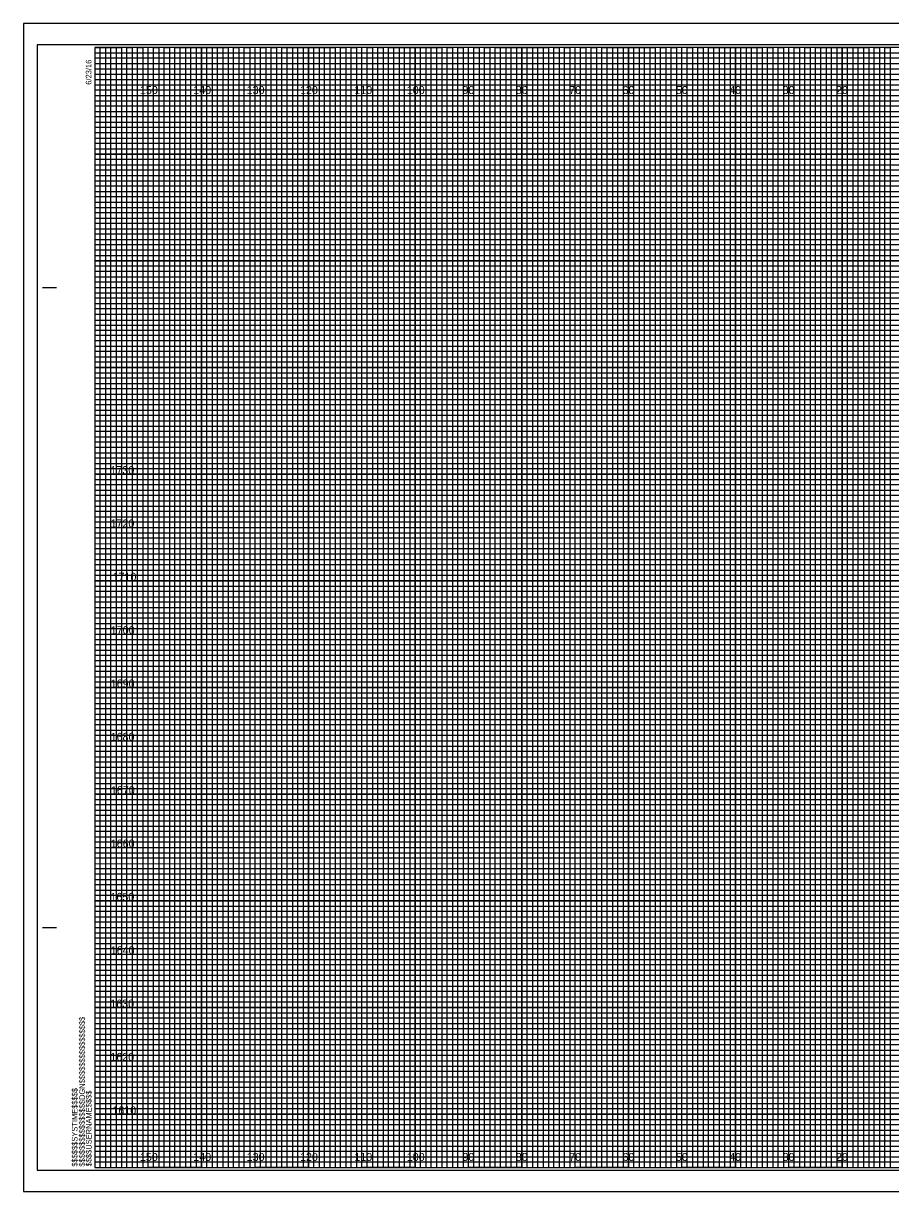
# Model space of a CAD drawing. Extents: x -13 to 323, y 435 to 654.
# Drawn here: x -13.4 to 149.1, y 435.5 to 654.5 of the extents above; entities that cross this region are included whole.
import ezdxf

# ---------------------------------------------------------------- set-up
doc = ezdxf.new("R2010")
doc.units = 0
for name, color, linetype in [('Exist Horizontal Alignment', 7, 'Continuous'), ('Exist XS Center Line Elevation Label', 7, 'Continuous'), ('Exist XS Ground Line', 7, 'Continuous'), ('Prop Study Area', 7, 'Continuous'), ('Prop XS Finish Grade', 7, 'Continuous'), ('Prop XS Finish Grade Pavement', 7, 'Continuous'), ('Prop XS Pvmt Edge Slope', 7, 'Continuous'), ('Prop XS Subgrade Earthwork', 7, 'Continuous'), ('Scratch_Level_0', 7, 'Continuous'), ('Scratch_Level_5', 7, 'Continuous'), ('Typical Guardrail CELL', 7, 'Continuous')]:
    doc.layers.add(name, color=color, linetype=linetype)

msp = doc.modelspace()

# ---------------------------------------------------------------- linework, layer by layer
at = {"layer": 'Exist Horizontal Alignment'}
for points in [[(0, 650), (5, 650), (5, 440), (15, 440), (15, 650), (25, 650), (25, 440), (35, 440), (35, 650), (45, 650), (45, 440), (55, 440), (55, 650), (65, 650), (65, 440), (75, 440), (75, 650), (85, 650), (85, 440), (95, 440), (95, 650), (105, 650), (105, 440), (115, 440), (115, 650), (125, 650), (125, 440), (135, 440), (135, 650), (145, 650), (145, 440), (155, 440)], [(0, 645), (275, 645)], [(0, 625), (320, 625), (320, 635), (0, 635)], [(0, 605), (320, 605), (320, 615), (0, 615)], [(0, 585), (320, 585), (320, 595), (0, 595)], [(0, 565), (320, 565), (320, 575), (0, 575)], [(0, 545), (320, 545), (320, 555), (0, 555)], [(0, 525), (320, 525), (320, 535), (0, 535)], [(0, 505), (320, 505), (320, 515), (0, 515)], [(0, 485), (320, 485), (320, 495), (0, 495)], [(0, 465), (320, 465), (320, 475), (0, 475)], [(0, 445), (320, 445), (320, 455), (0, 455)]]:
    msp.add_lwpolyline(points, dxfattribs=at)
at = {"layer": 'Exist XS Center Line Elevation Label'}
for points in [[(0, 440), (1, 440), (1, 650), (2, 650), (2, 440)], [(2, 440), (3, 440), (3, 650), (4, 650), (4, 440)], [(5, 440), (6, 440), (6, 650), (7, 650), (7, 440)], [(7, 440), (8, 440), (8, 650), (9, 650), (9, 440)], [(10, 440), (11, 440), (11, 650), (12, 650), (12, 440)], [(12, 440), (13, 440), (13, 650), (14, 650), (14, 440)], [(15, 440), (16, 440), (16, 650), (17, 650), (17, 440)], [(17, 440), (18, 440), (18, 650), (19, 650), (19, 440)], [(20, 440), (21, 440), (21, 650), (22, 650), (22, 440)], [(22, 440), (23, 440), (23, 650), (24, 650), (24, 440)], [(25, 440), (26, 440), (26, 650), (27, 650), (27, 440)], [(27, 440), (28, 440), (28, 650), (29, 650), (29, 440)], [(30, 440), (31, 440), (31, 650), (32, 650), (32, 440)], [(32, 440), (33, 440), (33, 650), (34, 650), (34, 440)], [(35, 440), (36, 440), (36, 650), (37, 650), (37, 440)], [(37, 440), (38, 440), (38, 650), (39, 650), (39, 440)], [(40, 440), (41, 440), (41, 650), (42, 650), (42, 440)], [(42, 440), (43, 440), (43, 650), (44, 650), (44, 440)], [(45, 440), (46, 440), (46, 650), (47, 650), (47, 440)], [(47, 440), (48, 440), (48, 650), (49, 650), (49, 440)], [(50, 440), (51, 440), (51, 650), (52, 650), (52, 440)], [(52, 440), (53, 440), (53, 650), (54, 650), (54, 440)], [(55, 440), (56, 440), (56, 650), (57, 650), (57, 440)], [(57, 440), (58, 440), (58, 650), (59, 650), (59, 440)], [(60, 440), (61, 440), (61, 650), (62, 650), (62, 440)], [(62, 440), (63, 440), (63, 650), (64, 650), (64, 440)], [(65, 440), (66, 440), (66, 650), (67, 650), (67, 440)], [(67, 440), (68, 440), (68, 650), (69, 650), (69, 440)], [(70, 440), (71, 440), (71, 650), (72, 650), (72, 440)], [(72, 440), (73, 440), (73, 650), (74, 650), (74, 440)], [(75, 440), (76, 440), (76, 650), (77, 650), (77, 440)], [(77, 440), (78, 440), (78, 650), (79, 650), (79, 440)], [(80, 440), (81, 440), (81, 650), (82, 650), (82, 440)], [(82, 440), (83, 440), (83, 650), (84, 650), (84, 440)], [(85, 440), (86, 440), (86, 650), (87, 650), (87, 440)], [(87, 440), (88, 440), (88, 650), (89, 650), (89, 440)], [(90, 440), (91, 440), (91, 650), (92, 650), (92, 440)], [(92, 440), (93, 440), (93, 650), (94, 650), (94, 440)], [(95, 440), (96, 440), (96, 650), (97, 650), (97, 440)], [(97, 440), (98, 440), (98, 650), (99, 650), (99, 440)], [(100, 440), (101, 440), (101, 650), (102, 650), (102, 440)], [(102, 440), (103, 440), (103, 650), (104, 650), (104, 440)], [(105, 440), (106, 440), (106, 650), (107, 650), (107, 440)], [(107, 440), (108, 440), (108, 650), (109, 650), (109, 440)], [(110, 440), (111, 440), (111, 650), (112, 650), (112, 440)], [(112, 440), (113, 440), (113, 650), (114, 650), (114, 440)], [(115, 440), (116, 440), (116, 650), (117, 650), (117, 440)], [(117, 440), (118, 440), (118, 650), (119, 650), (119, 440)], [(120, 440), (121, 440), (121, 650), (122, 650), (122, 440)], [(122, 440), (123, 440), (123, 650), (124, 650), (124, 440)], [(125, 440), (126, 440), (126, 650), (127, 650), (127, 440)], [(127, 440), (128, 440), (128, 650), (129, 650), (129, 440)], [(130, 440), (131, 440), (131, 650), (132, 650), (132, 440)], [(132, 440), (133, 440), (133, 650), (134, 650), (134, 440)], [(135, 440), (136, 440), (136, 650), (137, 650), (137, 440)], [(137, 440), (138, 440), (138, 650), (139, 650), (139, 440)], [(140, 440), (141, 440), (141, 650), (142, 650), (142, 440)], [(142, 440), (143, 440), (143, 650), (144, 650), (144, 440)], [(145, 440), (146, 440), (146, 650), (147, 650), (147, 440)], [(147, 440), (148, 440), (148, 650), (149, 650), (149, 440)]]:
    msp.add_lwpolyline(points, dxfattribs=at)
at = {"layer": 'Exist XS Ground Line'}
for p, q in [((-9.8, 605), (-7.3, 605)), ((-9.7, 605), (-7.2, 605)), ((-9.8, 485), (-7.3, 485)), ((-9.7, 485), (-7.2, 485)), ((0, 440), (0, 440)), ((0, 440), (0, 440)), ((0, 440), (0, 440)), ((0, 440), (0, 440)), ((0, 440), (0, 440)), ((0, 440), (0, 440)), ((0, 440), (0, 440))]:
    msp.add_line(p, q, dxfattribs=at)
msp.add_lwpolyline([(320, 650), (0, 650), (0, 440), (320, 440)], close=True, dxfattribs=at)
at = {"layer": 'Prop XS Finish Grade'}
msp.add_lwpolyline([(-10.8, 439.5), (322.4, 439.5), (322.4, 650.5), (-10.8, 650.5)], close=True, dxfattribs=at)
at = {"layer": 'Prop XS Finish Grade Pavement'}
msp.add_lwpolyline([(-13.4, 435.5), (323.3, 435.5), (323.3, 654.5), (-13.4, 654.5)], close=True, dxfattribs=at)
at = {"layer": 'Prop XS Pvmt Edge Slope'}
for p, q in [((323.3, 654.5), (-13.4, 654.5)), ((-13.4, 654.5), (-13.4, 435.5)), ((-13.4, 435.5), (323.3, 435.5))]:
    msp.add_line(p, q, dxfattribs=at)
at = {"layer": 'Scratch_Level_0'}
for p, q in [((10, 650), (0, 650)), ((10, 440), (10, 650)), ((30, 650), (20, 650)), ((20, 650), (20, 440)), ((30, 440), (30, 650)), ((50, 650), (40, 650)), ((40, 650), (40, 440)), ((50, 440), (50, 650)), ((70, 650), (60, 650)), ((60, 650), (60, 440)), ((70, 440), (70, 650)), ((90, 650), (80, 650)), ((80, 650), (80, 440)), ((90, 440), (90, 650)), ((110, 650), (100, 650)), ((100, 650), (100, 440)), ((110, 440), (110, 650)), ((130, 650), (120, 650)), ((120, 650), (120, 440)), ((130, 440), (130, 650)), ((150, 650), (140, 650)), ((140, 650), (140, 440)), ((20, 440), (10, 440)), ((40, 440), (30, 440)), ((60, 440), (50, 440)), ((80, 440), (70, 440)), ((100, 440), (90, 440)), ((120, 440), (110, 440)), ((140, 440), (130, 440))]:
    msp.add_line(p, q, dxfattribs=at)
for points in [[(0, 640), (320, 640), (320, 630), (0, 630)], [(0, 620), (320, 620), (320, 610), (0, 610)], [(0, 600), (320, 600), (320, 590), (0, 590)], [(0, 580), (320, 580), (320, 570), (0, 570)], [(0, 560), (320, 560), (320, 550), (0, 550)], [(0, 540), (320, 540), (320, 530), (0, 530)], [(0, 520), (320, 520), (320, 510), (0, 510)], [(0, 500), (320, 500), (320, 490), (0, 490)], [(0, 480), (320, 480), (320, 470), (0, 470)], [(0, 460), (320, 460), (320, 450), (0, 450)]]:
    msp.add_lwpolyline(points, dxfattribs=at)
at = {"layer": 'Scratch_Level_5'}
for p, q in [((0, 649), (260, 649)), ((260, 647.98), (0, 647.98)), ((0, 647.98), (0, 647)), ((0, 647), (260, 647)), ((260, 645.89), (0, 645.89)), ((0, 645.89), (0, 644)), ((0, 644), (320, 644))]:
    msp.add_line(p, q, dxfattribs=at)
for points in [[(0, 643), (270, 643), (320, 643), (320, 642), (0, 642)], [(0, 641), (320, 641), (320, 639), (0, 639)], [(0, 638), (320, 638), (320, 637), (0, 636.98)], [(0, 636), (320, 636), (320, 634), (0, 634)], [(0, 633), (320, 633), (320, 632), (0, 632)], [(0, 631), (320, 631), (320, 629), (0, 629)], [(0, 628), (320, 628), (320, 627), (0, 627)], [(0, 626), (320, 626), (320, 624), (0, 624)], [(0, 623), (320, 623), (320, 622), (0, 622)], [(0, 621), (320, 621), (320, 619), (0, 619)], [(0, 618), (320, 618), (320, 617), (0, 617)], [(0, 616), (320, 616), (320, 613.95), (320, 613), (320, 612), (0, 612)], [(0, 614), (320, 614), (320, 613), (0, 613)], [(0, 611), (320, 611), (320, 609), (0, 609.03)], [(0, 609.03), (320, 609), (320, 608), (0, 608)], [(0, 607), (320, 607), (320, 606), (0, 606)], [(0, 604), (320, 604), (320, 603), (0, 603)], [(0, 602), (320, 602), (320, 601), (0, 601)], [(-0.07, 598.89), (320, 598.89), (320, 597.88), (-0.07, 597.88)], [(0, 597), (320, 597), (320, 596), (0, 596)], [(0, 594), (320, 594), (320, 593), (0, 593)], [(0, 592), (320, 592), (320, 591), (0, 591)], [(0, 589), (320, 589), (320, 588), (0, 588)], [(0, 587), (320, 587), (320, 586), (0, 586)], [(0, 584), (320, 584), (320, 583), (0, 583)], [(0, 582), (320, 582), (320, 581), (0, 581)], [(0, 579), (320, 579), (319.99, 577.98), (0, 578)], [(0, 577), (320, 577), (320, 576), (0, 576)], [(0, 574), (320, 574), (320, 573), (0, 573)], [(0, 572), (320, 572), (320, 571), (0, 571)], [(0, 569), (320, 569), (320, 568), (0, 568)], [(0, 567), (320, 567), (320, 566), (0, 566)], [(0, 564), (320, 564), (320, 563), (0, 563)], [(0, 562), (320, 562), (320, 561), (0, 561)], [(0, 559), (320, 559), (320, 558), (0, 558)], [(0, 556.99), (320.07, 556.91), (320, 556), (0, 556)], [(0, 554), (320, 554), (320, 553), (0, 553)], [(0, 552), (320, 552), (320, 551), (0, 551)], [(0, 549), (320, 549), (320, 548), (0, 548)], [(0, 547), (320, 547), (320, 546), (0, 546)], [(0, 544), (320, 544), (320, 543), (0, 543)], [(0, 542), (320, 542), (320, 541), (0, 541)], [(0, 539), (320, 539), (320, 538), (0, 538)], [(0, 537), (320, 537), (320, 536), (0, 536)], [(0, 534), (320, 534), (320, 533), (0, 533)], [(0, 532), (320, 532), (320, 531), (0, 531)], [(0, 529), (320, 529), (320, 528), (0, 528)], [(0, 527), (320, 527), (320, 526), (0, 526)], [(0, 524), (320, 524), (320, 523), (0, 523)], [(0, 522), (320, 522), (320, 521), (0, 521)], [(0, 519), (320, 519), (319.99, 517.98), (0, 518)], [(0, 517), (320, 517), (320, 516), (0, 516)], [(0, 514), (320, 514), (320, 513), (0, 513)], [(0, 512), (320, 512), (320, 511), (0, 511)], [(0, 509), (320, 509), (320, 508), (0, 508)], [(0, 507), (320, 507), (320, 506), (0, 506)], [(0, 504), (320, 504), (320, 503), (0, 503)], [(0, 502), (320, 502), (320, 501), (0, 501)], [(0, 499), (320, 499), (320, 498), (0, 498)], [(0, 496.99), (320.07, 496.91), (320, 496), (0, 496)], [(0, 494), (320, 494), (320, 493), (0, 493)], [(0, 492), (320, 492), (320, 491), (0, 491)], [(0, 489), (320, 489), (320, 488), (0, 488)], [(0, 487), (320, 487), (320, 486), (0, 486)], [(0, 484), (320, 484), (320, 483), (0, 483)], [(0, 482), (320, 482), (320, 481), (0, 481)], [(0, 479), (320, 479), (320, 478), (0, 478)], [(0, 477), (320, 477), (320, 476), (0, 476)], [(0, 474), (320, 474), (320, 473), (0, 473)], [(0, 472), (320, 472), (320, 471), (0, 471)], [(0, 469), (320, 469), (320, 468), (0, 468)], [(0, 467), (320, 467), (320, 466), (0, 466)], [(0, 464), (320, 464), (320, 463), (0, 463)], [(0, 462), (320, 462), (320, 461), (0, 461)], [(0, 459), (320, 459), (320, 458), (0, 458)], [(0, 457), (320, 457), (320, 456), (0, 456)], [(0, 454), (320, 454), (320, 453), (0, 453)], [(0, 452), (320, 452), (320, 451), (0, 451)], [(0, 449), (320, 449), (320, 448), (0, 448)], [(0, 447), (320, 447), (320, 446), (0, 446)], [(0, 444), (320, 444), (320, 443), (0, 443)], [(0, 442), (320, 442), (320, 441), (0, 441)]]:
    msp.add_lwpolyline(points, dxfattribs=at)
at = {"layer": 'Typical Guardrail CELL'}
for p, q in [((10, 440), (10, 650)), ((20, 440), (20, 650)), ((30, 440), (30, 650)), ((40, 440), (40, 650)), ((50, 440), (50, 650)), ((60, 440), (60, 650)), ((70, 440), (70, 650)), ((80, 440), (80, 650)), ((90, 440), (90, 650)), ((100, 440), (100, 650)), ((110, 440), (110, 650)), ((120, 440), (120, 650)), ((130, 440), (130, 650)), ((140, 440), (140, 650)), ((0, 640), (320, 640)), ((0, 630), (320, 630)), ((0, 620), (320, 620)), ((0, 610), (320, 610)), ((0, 600), (320, 600)), ((0, 590), (320, 590)), ((0, 580), (320, 580)), ((0, 570), (320, 570)), ((0, 560), (320, 560)), ((0, 550), (320, 550)), ((0, 540), (320, 540)), ((0, 530), (320, 530)), ((0, 520), (320, 520)), ((0, 510), (320, 510)), ((0, 500), (320, 500)), ((0, 490), (320, 490)), ((0, 480), (320, 480)), ((0, 470), (320, 470)), ((0, 460), (320, 460)), ((0, 450), (320, 450))]:
    msp.add_line(p, q, dxfattribs=at)

# ---------------------------------------------------------------- texts
at = {"layer": 'Exist XS Ground Line'}
for s, p in [('6/23/16', (-0.65, 643)), ('$$$$$$$$$$$$$$$$DGN$$$$$$$$$$$$$$$$', (-1.88, 440.18)), ('$$$$$$SYSTIME$$$$$', (-3.26, 440.18)), ('$$$$USERNAME$$$$', (-0.62, 440.23))]:
    msp.add_text(s, height=1.05, rotation=90, dxfattribs=at).set_placement(p)
at = {"layer": 'Prop Study Area'}
for s, p in [('150', (8.44, 641.25)), ('140', (18.44, 641.25)), ('130', (28.44, 641.25)), ('120', (38.44, 641.25)), ('110', (48.62, 641.25)), ('100', (58.44, 641.25)), ('90', (68.86, 641.25)), ('80', (78.86, 641.25)), ('70', (88.86, 641.25)), ('60', (98.86, 641.25)), ('50', (108.86, 641.25)), ('40', (118.86, 641.25)), ('30', (128.86, 641.25)), ('20', (138.86, 641.25)), ('150', (8.44, 441.25)), ('140', (18.44, 441.25)), ('130', (28.44, 441.25)), ('120', (38.44, 441.25)), ('110', (48.62, 441.25)), ('100', (58.44, 441.25)), ('90', (68.86, 441.25)), ('80', (78.86, 441.25)), ('70', (88.86, 441.25)), ('60', (98.86, 441.25)), ('50', (108.86, 441.25)), ('40', (118.86, 441.25)), ('30', (128.86, 441.25)), ('20', (138.86, 441.25))]:
    msp.add_text(s, height=1.5, dxfattribs=at).set_placement(p)
at = {"layer": 'Prop XS Subgrade Earthwork'}
for s, p in [('1730', (2.92, 570)), ('1720', (2.93, 560)), ('1710', (3.31, 550)), ('1700', (2.98, 540)), ('1690', (2.97, 530)), ('1680', (2.95, 520)), ('1670', (3, 510)), ('1660', (2.97, 500)), ('1650', (2.92, 490)), ('1640', (2.97, 480)), ('1630', (2.89, 470)), ('1620', (2.9, 460)), ('1610', (3.28, 450))]:
    msp.add_text(s, height=1.5, dxfattribs=at).set_placement(p)

doc.saveas('drawing.dxf')
